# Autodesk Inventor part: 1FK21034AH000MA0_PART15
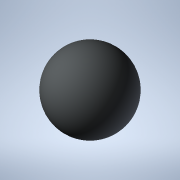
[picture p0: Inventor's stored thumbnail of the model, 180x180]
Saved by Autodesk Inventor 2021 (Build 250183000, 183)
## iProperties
Created: 2025-04
Part Number: 1FK21034AH000MA0_PART15
Material: Generic
Catalog Web Link: www.3dfindit.com
Description: -Servo synchronous motor
Document SubType Name: Modeling
Designer: psAdmin
Mass: 0.113097 g
Surface Area: 1.13097 cm^2
Volume: 0.113097 cm^3
Density: 1 g/cm^3
Appearance: PSOLRGB-212-217-219
Category: PARTsolutions
Title: 1FK21034AH000MA0_PART15
Author: Cadenas PARTsolutions
Comments: Servo synchronous motor
Sending System: PARTsolutions
Preprocessor: ST-DEVELOPER v19.3
PSOL_IDENT_0: {$CADENAS_DATA/23d-libs/siemens_ag/_cat_/ec/b7/1fk21034ah000ma0.prj},216 {VTYP=3D},{NB=1FK21034AH000
PSOL_IDENT_1: MA0_PART15},{LINA=1FK21034AH000MA0_PART15},{NN=1FK21034AH000MA0_PART15},{NOPRJ=TRUE},{DATE=19.08.202
PSOL_IDENT_2: 5 14:01:05},{GEOMDATE=30.07.2025 02:01:02},{VERSION=},{LINEID=10},{WBVAR=},{WBNUMERIC=}  {NB=1FK2103
PSOL_IDENT_3: 4AH000MA0_PART15},{LINA=1FK21034AH000MA0_PART15},{KT=DUMMY},{PREVIEW=../../../_pool_/7c/50/p_d211_xx
PSOL_IDENT_4: _00932j.png},{DESCSHORT=SIMOTICS S-1FK2 HD, SINAMICS S210 3AC 400V-480V, 1.01 Nm, 4500 rpm},{DESCLON
PSOL_IDENT_5: G=SIMOTICS S-1FK2 HD servo motor M0=1.27 Nm; PN = 0.48 kW at nN=4500 rpm (380-480 V); PN = 0.3 kW at
PSOL_IDENT_6: nN=2500 rpm (200-240 V); degree of protection IP64; cylindrical shaft D14 x 30 mm; absolute encoder
PSOL_IDENT_7: 22-bit + 12-bit multiturn (encoder AM22DQC); with OCC interface; plug size M17, rotatable; SIMOTICS
PSOL_IDENT_8: S-1FK2 servomotorfor a wide range of uses in industrial environments. SIMOTICS S‑1FK2 servomotors a
PSOL_IDENT_9: re compact synchronous motors with a high dynamic performance that set themselves apart as a result
PSOL_IDENT_10: of their high power density, degree of protection and overload capability. The motors are available
PSOL_IDENT_11: in two variants: as High Dynamic variant (highest dynamic performance as a result of the low intrins
PSOL_IDENT_12: ic moment of inertia for applications demanding a high dynamic performance with low moved masses) -
PSOL_IDENT_13: and as Compact variant (precise and stable closed-loop control for medium up to large moved masses a
PSOL_IDENT_14: s a result of a medium intrinsic moment of inertia). SIMOTICSS‑1FK2 servomotors fully exploit their
PSOL_IDENT_15: strengths in a system with the SINAMICSS210 frequency converter and simple connection using the one
PSOL_IDENT_16: cable connection (OCC). Advantages include the short control and positioning times, fast and precise
PSOL_IDENT_17: correction of disturbing quantities as well as stable control with a high dynamic performance. The
PSOL_IDENT_18: servo motors can be configured to address a wide range of requirements. For example with and without
PSOL_IDENT_19: holding brake, IP64 or IP65 degree of protection, singleturn or multiturn absolute encoders - to na
PSOL_IDENT_20: me just a few. Further, the servomotors are available in different shaft heights extending from 20 t
PSOL_IDENT_21: o 100. A shaft sealing ring is available to achieve an IP65 degree of protection and for subsequent
PSOL_IDENT_22: mounting at the motor or as spare part. SIMOTICS - the optimum motor for each and every motion contr
PSOL_IDENT_23: ol application.},{INTNO=4034106444822},{SUPPLIERALTNO=1FK2103-4AH00-0MA0},{MANUID=1FK21034AH000MA0},
PSOL_IDENT_24: {MANUNAME=Siemens},{MANUTYPEDESC=SYNCHRONOUS MOTOR 1FK2 HD 1,27 NM},{AAU732=SIMOTICS},{AAO057=S-1FK2
PSOL_IDENT_25: },{AAU734=SIMOTICS S-1FK2 HD servo motor M0=1.27 Nm; PN = 0.48 kW at nN=4500 rpm (380-480 V); PN = 0
PSOL_IDENT_26: .3 kW at nN=2500 rpm (200-240 V); degree of protection IP64; cylindrical shaft D14 x 30 mm; absolute
PSOL_IDENT_27: encoder 22-bit + 12-bit multiturn (encoder AM22DQC); with OCC interface; plug size M17, rotatable;}
PSOL_IDENT_28: ,{AAW338=SYNCHRONOUS MOTOR 1FK2 HD 1,27 NM},{AAO742=SIMOTICS},{AAO663=4034106444822},{NOCUPEROU=1},{
PSOL_IDENT_29: PRICEQUANTITY=1},{QUANTITYMIN=1},{QUANTITYINT=1},{CTN=85015100},{COO=RO},{AAO676=1FK2103-4AH00-0MA0}
PSOL_IDENT_30: ,{AAO677=Siemens AG},{ORDERUNIT=C62},{CONTENTUNIT=C62}
NB: 1FK21034AH000MA0_PART15
NT: Servo synchronous motor
NBSYN: $MANUID._PART15
LINA: 1FK21034AH000MA0_PART15
CATALOG: SIEMENS
PREVIEW: ../../../_pool_/7c/50/p_d211_xx_00932j.png
DESCSHORT: SIMOTICS S-1FK2 HD, SINAMICS S210 3AC 400V-480V, 1.01 Nm, 4500 rpm
DESCLONG: SIMOTICS S-1FK2 HD servo motor M0=1.27 Nm; PN = 0.48 kW at nN=4500 rpm (380-480 V); PN = 0.3 kW at nN=2500 rpm (200-240 V); degree of protection IP64; cylindric
INTNO: 4034106444822
SUPPLIERALTNO: 1FK2103-4AH00-0MA0
MANUID: 1FK21034AH000MA0
MANUNAME: Siemens
MANUTYPEDESC: SYNCHRONOUS MOTOR 1FK2 HD 1,27 NM
AAU732: SIMOTICS
AAO057: S-1FK2
AAU734: SIMOTICS S-1FK2 HD servo motor M0=1.27 Nm; PN = 0.48 kW at nN=4500 rpm (380-480 V); PN = 0.3 kW at nN=2500 rpm (200-240 V); degree of protection IP64; cylindric
AAW338: SYNCHRONOUS MOTOR 1FK2 HD 1,27 NM
AAO742: SIMOTICS
AAO663: 4034106444822.0
NOCUPEROU: 1
PRICEQUANTITY: 1
QUANTITYMIN: 1
QUANTITYINT: 1
CTN: 85015100
COO: RO
ARTICLENO: 1FK21034AH000MA0_PART15
BOMINFO: 1FK21034AH000MA0_PART15
CREATOR: CADENAS GmbH
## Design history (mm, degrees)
feature "2025_04_17_15_01_37_0314"
body "Solid1"
